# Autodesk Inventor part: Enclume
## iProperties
Author: Flavien MARTY
Shininess: 86.0
PropertySet Name: _Private Model Information
Created: 2001-10
Part Number: Enclume
Material: Par défaut
Document SubType Name: Modélisation
Designer: Flavien MARTY
Control State: 0
Master: False
Checked Out: False
PropertySet Name: Design Tracking Control
Density: 0.0
Volumn: 0.0
Area: 0.0
PropertySet Name: Model Information
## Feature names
1. Base1
